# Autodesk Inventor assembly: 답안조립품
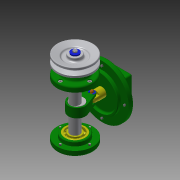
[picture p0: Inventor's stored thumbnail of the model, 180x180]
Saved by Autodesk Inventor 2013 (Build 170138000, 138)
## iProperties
Created: 2018-02
Part Number: 답안조립품
Document SubType Name: Assembly
Designer: Administrator
Author: Administrator
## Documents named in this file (18)
- C:\Users\Administrator\Desktop\480208V1013\답안조립품.iam
- C:\Users\Administrator\Desktop\480208V1013\본체.ipt
- C:\Users\Administrator\Desktop\480208V1013\E-링.ipt
- C:\Users\Administrator\Desktop\480208V1013\V-벨트풀리.ipt
- C:\Users\Administrator\Desktop\480208V1013\덮개.ipt
- C:\Users\Administrator\Desktop\480208V1013\뒤커버.ipt
- C:\Users\Administrator\Desktop\480208V1013\링크.ipt
- C:\Users\Administrator\Desktop\480208V1013\베어링 17 x 40 x 12.ipt
- C:\Users\Administrator\Desktop\480208V1013\볼트 M4 x 8.ipt
- C:\Users\Administrator\Desktop\480208V1013\볼트 M4 x 10.ipt
- C:\Users\Administrator\Desktop\480208V1013\슬라이더.ipt
- C:\Users\Administrator\Desktop\480208V1013\앞커버.ipt
- C:\Users\Administrator\Desktop\480208V1013\오일 실 17 30 8.ipt
- C:\Users\Administrator\Desktop\480208V1013\와셔 4x16.ipt
- C:\Users\Administrator\Desktop\480208V1013\클레비스 핀 6 x 22.ipt
- 클레비스 핀 6 x 22.ipt
- C:\Users\Administrator\Desktop\480208V1013\키 4 x 4 x 12.ipt
- C:\Users\Administrator\Desktop\480208V1013\편심축.ipt
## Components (2 placed, 2 different names)
1. E-링:1
2. V-벨트풀리:1
